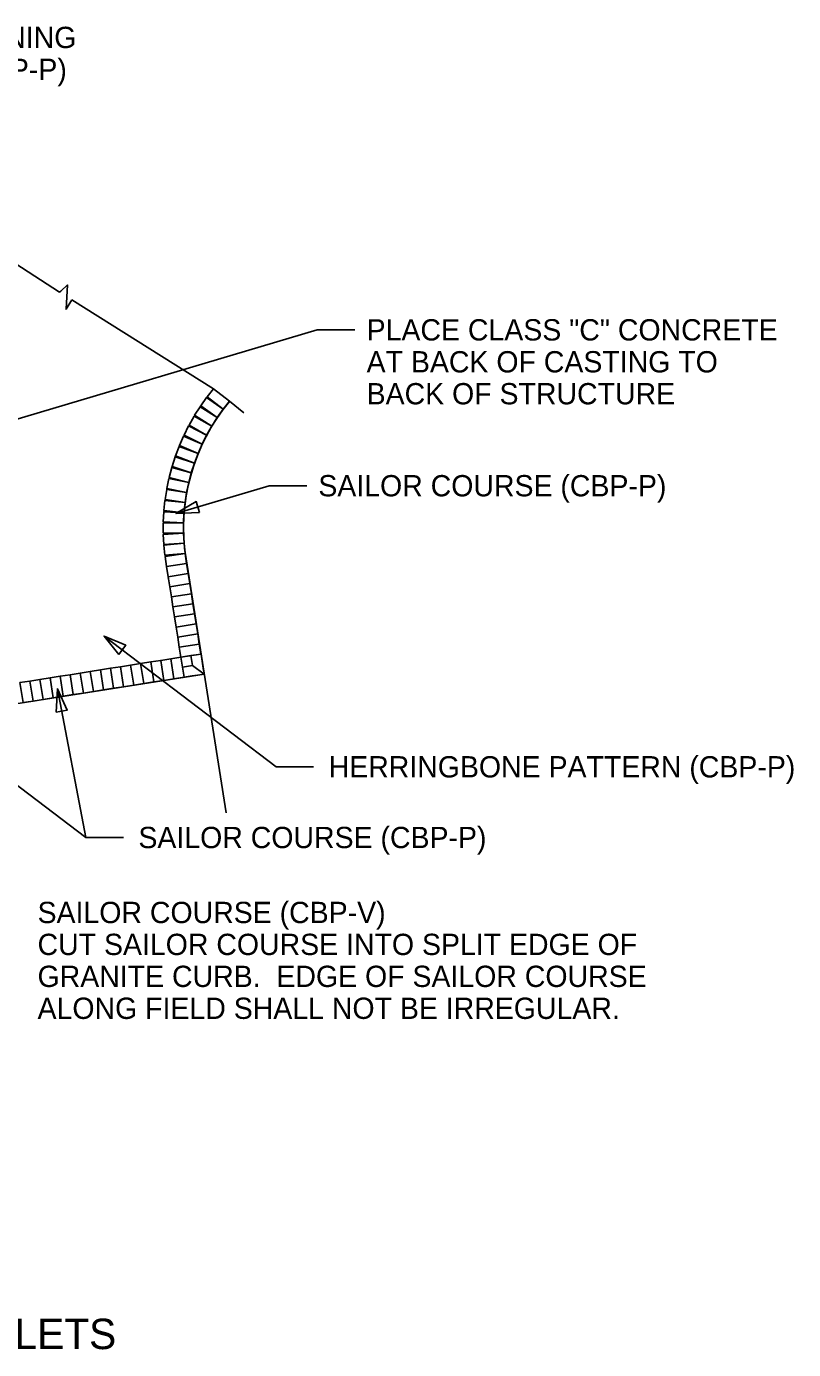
# Model space of a CAD drawing. Extents: x -848 to 1, y -1131 to -115.
# Drawn here: x -607.2 to -556.7, y -781.6 to -694.6 of the extents above; entities that cross this region are included whole.
import ezdxf

# ---------------------------------------------------------------- set-up
doc = ezdxf.new("R2010")
doc.units = 0
for name, color, linetype in [('PV_P_Curb', 7, 'Continuous'), ('PV_P_Joint', 7, 'Continuous'), ('SH_Text', 7, 'Continuous'), ('TX_X_5', 7, 'Continuous')]:
    doc.layers.add(name, color=color, linetype=linetype)

msp = doc.modelspace()

# ---------------------------------------------------------------- linework, layer by layer
at = {"layer": 'PV_P_Curb'}
msp.add_line((-594.051, -746.322), (-596.686, -729.609), dxfattribs=at)
msp.add_arc((-583.845, -727.583), 13, 140.17518, 188.96168, dxfattribs=at)
at = {"layer": 'PV_P_Joint'}
for p, q in [((-604.995, -712.074), (-616.532, -704.617)), ((-604.995, -712.074), (-612.371, -707.307)), ((-594.878, -718.428), (-604.195, -712.576)), ((-595.722, -719.554), (-595.334, -719.008)), ((-595.334, -719.008), (-595.292, -718.955)), ((-593.835, -719.253), (-592.884, -720.012)), ((-594.999, -720.89), (-596.12, -720.176)), ((-595.759, -719.611), (-595.722, -719.554)), ((-597.398, -722.905), (-597.378, -722.845)), ((-597.398, -722.905), (-597.378, -722.845)), ((-597.141, -722.218), (-597.116, -722.152)), ((-597.141, -722.218), (-597.116, -722.152)), ((-597.623, -723.611), (-597.605, -723.543)), ((-597.623, -723.611), (-597.605, -723.543)), ((-597.22, -726.562), (-597.188, -726.543)), ((-597.857, -730.788), (-597.961, -730.126)), ((-597.753, -731.45), (-597.857, -730.788)), ((-597.832, -730.946), (-597.868, -730.91)), ((-597.648, -732.112), (-597.753, -731.45)), ((-597.544, -732.774), (-597.648, -732.112)), ((-597.439, -733.435), (-597.544, -732.774)), ((-597.335, -734.097), (-597.439, -733.435)), ((-597.231, -734.759), (-597.335, -734.097)), ((-597.126, -735.421), (-597.231, -734.759)), ((-597.022, -736.083), (-597.126, -735.421)), ((-602.317, -736.918), (-601.655, -736.813)), ((-601.655, -736.813), (-600.993, -736.709)), ((-600.993, -736.709), (-600.331, -736.605)), ((-599.669, -736.5), (-599.007, -736.396)), ((-599.007, -736.396), (-598.346, -736.291)), ((-598.346, -736.291), (-597.684, -736.187)), ((-597.684, -736.187), (-597.022, -736.083)), ((-596.257, -736.63), (-595.501, -737.189)), ((-619.198, -740.926), (-595.491, -737.188)), ((-607.611, -737.753), (-606.949, -737.648)), ((-606.949, -737.648), (-606.287, -737.544)), ((-606.287, -737.544), (-605.626, -737.44)), ((-605.626, -737.44), (-604.964, -737.335)), ((-604.964, -737.335), (-604.302, -737.231)), ((-604.302, -737.231), (-603.64, -737.126)), ((-603.64, -737.126), (-602.978, -737.022)), ((-603.054, -737.034), (-603.033, -737.013)), ((-602.978, -737.022), (-602.317, -736.918))]:
    msp.add_line(p, q, dxfattribs=at)
for points in [[(-604.995, -712.074), (-604.92, -712.005), (-604.481, -711.598), (-604.572, -713.198), (-604.195, -712.576)], [(-604.195, -712.576), (-604.572, -713.198), (-604.481, -711.598), (-604.92, -712.005), (-604.995, -712.074)], [(-594.878, -718.428), (-604.195, -712.576)], [(-595.292, -718.955), (-595.294, -718.954), (-594.878, -718.428)], [(-595.292, -718.955), (-595.294, -718.954), (-594.878, -718.428)], [(-595.759, -719.611), (-595.722, -719.554), (-595.334, -719.008), (-595.292, -718.955)], [(-595.328, -721.473), (-596.486, -720.82), (-596.157, -720.236), (-594.999, -720.89)], [(-596.12, -720.176), (-595.761, -719.61), (-595.759, -719.611)], [(-596.12, -720.176), (-595.761, -719.61), (-595.759, -719.611)], [(-596.12, -720.176), (-596.12, -720.176)], [(-595.628, -722.072), (-596.817, -721.476), (-596.517, -720.877), (-595.328, -721.473)], [(-597.116, -722.152), (-596.846, -721.538), (-596.845, -721.539)], [(-597.116, -722.152), (-596.846, -721.538), (-596.845, -721.539), (-595.628, -722.072)], [(-597.605, -723.543), (-597.399, -722.905), (-597.398, -722.905)], [(-597.605, -723.543), (-597.399, -722.905), (-597.398, -722.905)], [(-597.378, -722.845), (-597.142, -722.218), (-597.141, -722.218)], [(-597.378, -722.845), (-597.142, -722.218), (-597.141, -722.218)], [(-597.796, -724.258), (-597.625, -723.61), (-597.623, -723.611)], [(-596.51, -724.598), (-597.796, -724.258), (-597.625, -723.61), (-597.623, -723.611)], [(-596.645, -725.255), (-597.948, -724.989), (-597.814, -724.332), (-596.51, -724.598)], [(-596.749, -725.917), (-598.063, -725.709), (-597.958, -725.047), (-596.645, -725.255)], [(-597.188, -726.543), (-598.144, -726.438), (-598.071, -725.772), (-596.749, -725.917)], [(-596.857, -727.922), (-598.187, -727.923), (-598.188, -727.253), (-596.858, -727.252)], [(-596.858, -727.252), (-598.186, -727.181), (-598.15, -726.512), (-597.22, -726.562)], [(-596.814, -728.59), (-598.141, -728.675), (-598.184, -728.006), (-596.857, -727.922)], [(-596.752, -729.257), (-598.076, -729.381), (-598.138, -728.714), (-596.814, -728.59)], [(-597.961, -730.126), (-598.066, -729.465), (-596.752, -729.257)], [(-601.105, -735.895), (-602.072, -734.688), (-600.651, -735.298), (-600.878, -735.596), (-601.105, -735.895)], [(-596.153, -737.292), (-596.815, -737.397), (-597.022, -736.083), (-596.36, -735.978), (-596.257, -736.63)], [(-596.277, -736.506), (-596.36, -735.978), (-595.698, -735.874), (-595.528, -736.957)], [(-600.331, -736.605), (-599.687, -736.503), (-599.669, -736.5)], [(-595.501, -737.189), (-596.815, -737.397), (-596.919, -736.735), (-596.257, -736.63)]]:
    msp.add_lwpolyline(points, dxfattribs=at)
for points in [[(-594.878, -718.428), (-593.835, -719.253), (-594.25, -719.779), (-595.294, -718.954)], [(-595.334, -719.008), (-594.25, -719.779), (-594.639, -720.325), (-595.722, -719.554)], [(-596.157, -720.236), (-594.999, -720.89), (-595.328, -721.473), (-596.486, -720.82)], [(-595.761, -719.61), (-594.639, -720.325), (-594.999, -720.89), (-596.12, -720.176)], [(-596.517, -720.877), (-595.328, -721.473), (-595.628, -722.072), (-596.817, -721.476)], [(-596.846, -721.538), (-595.628, -722.072), (-595.897, -722.686), (-597.116, -722.152)], [(-597.399, -722.905), (-596.133, -723.313), (-596.339, -723.951), (-597.605, -723.543)], [(-597.142, -722.218), (-595.897, -722.686), (-596.133, -723.313), (-597.378, -722.845)], [(-597.625, -723.61), (-596.339, -723.951), (-596.51, -724.598), (-597.796, -724.258)], [(-597.814, -724.332), (-596.51, -724.598), (-596.645, -725.255), (-597.948, -724.989)], [(-597.958, -725.047), (-596.645, -725.255), (-596.749, -725.917), (-598.063, -725.709)], [(-598.071, -725.772), (-596.749, -725.917), (-596.822, -726.583), (-598.144, -726.438)], [(-598.188, -727.253), (-596.858, -727.252), (-596.857, -727.922), (-598.187, -727.923)], [(-598.15, -726.512), (-596.822, -726.583), (-596.858, -727.252), (-598.186, -727.181)], [(-598.184, -728.006), (-596.857, -727.922), (-596.814, -728.59), (-598.141, -728.675)], [(-598.138, -728.714), (-596.814, -728.59), (-596.752, -729.257), (-598.076, -729.381)], [(-598.066, -729.465), (-596.752, -729.257), (-596.648, -729.919), (-597.961, -730.126)], [(-597.961, -730.126), (-596.648, -729.919), (-596.543, -730.581), (-597.857, -730.788)], [(-597.857, -730.788), (-596.543, -730.581), (-596.439, -731.243), (-597.753, -731.45)], [(-597.753, -731.45), (-596.439, -731.243), (-596.334, -731.905), (-597.648, -732.112)], [(-597.648, -732.112), (-596.334, -731.905), (-596.23, -732.566), (-597.544, -732.774)], [(-597.544, -732.774), (-596.23, -732.566), (-596.126, -733.228), (-597.439, -733.435)], [(-597.439, -733.435), (-596.126, -733.228), (-596.021, -733.89), (-597.335, -734.097)], [(-597.335, -734.097), (-596.021, -733.89), (-595.917, -734.552), (-597.231, -734.759)], [(-597.231, -734.759), (-595.917, -734.552), (-595.813, -735.214), (-597.126, -735.421)], [(-597.126, -735.421), (-595.813, -735.214), (-595.708, -735.876), (-597.022, -736.083)], [(-602.109, -738.231), (-602.317, -736.918), (-601.655, -736.813), (-601.448, -738.127)], [(-601.448, -738.127), (-601.655, -736.813), (-600.993, -736.709), (-600.786, -738.023)], [(-600.786, -738.023), (-600.993, -736.709), (-600.331, -736.605), (-600.124, -737.918)], [(-600.124, -737.918), (-600.331, -736.605), (-599.669, -736.5), (-599.462, -737.814)], [(-599.462, -737.814), (-599.669, -736.5), (-599.007, -736.396), (-598.8, -737.71)], [(-598.8, -737.71), (-599.007, -736.396), (-598.346, -736.291), (-598.138, -737.605)], [(-598.138, -737.605), (-598.346, -736.291), (-597.684, -736.187), (-597.477, -737.501)], [(-597.477, -737.501), (-597.684, -736.187), (-597.022, -736.083), (-596.815, -737.397)], [(-607.404, -739.066), (-607.611, -737.753), (-606.949, -737.648), (-606.742, -738.962)], [(-606.742, -738.962), (-606.949, -737.648), (-606.287, -737.544), (-606.08, -738.858)], [(-606.742, -738.962), (-606.949, -737.648), (-606.287, -737.544), (-606.08, -738.858)], [(-606.08, -738.858), (-606.287, -737.544), (-605.626, -737.44), (-605.418, -738.753)], [(-605.418, -738.753), (-605.626, -737.44), (-604.964, -737.335), (-604.757, -738.649)], [(-604.757, -738.649), (-604.964, -737.335), (-604.302, -737.231), (-604.095, -738.545)], [(-604.095, -738.545), (-604.302, -737.231), (-603.64, -737.126), (-603.433, -738.44)], [(-603.433, -738.44), (-603.64, -737.126), (-602.978, -737.022), (-602.771, -738.336)], [(-602.771, -738.336), (-602.978, -737.022), (-602.317, -736.918), (-602.109, -738.231)]]:
    msp.add_lwpolyline(points, close=True, dxfattribs=at)
at = {"layer": 'TX_X_5'}
for p, q in [((-619.244, -723.841), (-588.068, -714.553)), ((-585.594, -714.553), (-588.068, -714.553)), ((-597.348, -726.637), (-591.226, -724.814)), ((-588.752, -724.814), (-591.226, -724.814)), ((-602.072, -734.688), (-590.769, -743.289)), ((-618.566, -736.302), (-603.276, -747.937)), ((-605.143, -738.154), (-603.276, -747.937)), ((-588.295, -743.289), (-590.769, -743.289)), ((-600.802, -747.937), (-603.276, -747.937))]:
    msp.add_line(p, q, dxfattribs=at)
for points in [[(-595.803, -726.569), (-597.348, -726.637), (-596.017, -725.85)], [(-601.105, -735.895), (-602.072, -734.688), (-600.651, -735.298)], [(-605.23, -739.698), (-605.143, -738.154), (-604.493, -739.558)]]:
    msp.add_lwpolyline(points, close=True, dxfattribs=at)

# ---------------------------------------------------------------- texts
at = {"layer": 'SH_Text'}
msp.add_text('TYPICAL PAVER PATTERN LAYOUT AT STORM INLETS', height=2, dxfattribs=at).set_placement((-671.566, -781.579))
at = {"layer": 'TX_X_5'}
for s, p in [('SINGLE RUNNING', (-620.019, -696.027)), ('COURSE (CBP-P)', (-620.019, -698.127)), ('PLACE CLASS "C" CONCRETE', (-584.81, -715.256)), ('AT BACK OF CASTING TO', (-584.81, -717.356)), ('BACK OF STRUCTURE', (-584.81, -719.456)), ('SAILOR COURSE (CBP-P)', (-587.985, -725.506)), ('HERRINGBONE PATTERN (CBP-P)', (-587.308, -743.989)), ('SAILOR COURSE (CBP-P)', (-599.816, -748.637)), ('SAILOR COURSE (CBP-V)', (-606.447, -753.567)), ('CUT SAILOR COURSE INTO SPLIT EDGE OF', (-606.447, -755.667)), ('GRANITE CURB.  EDGE OF SAILOR COURSE', (-606.447, -757.767)), ('ALONG FIELD SHALL NOT BE IRREGULAR.', (-606.447, -759.867))]:
    msp.add_text(s, height=1.4, dxfattribs=at).set_placement(p)

doc.saveas('drawing.dxf')
